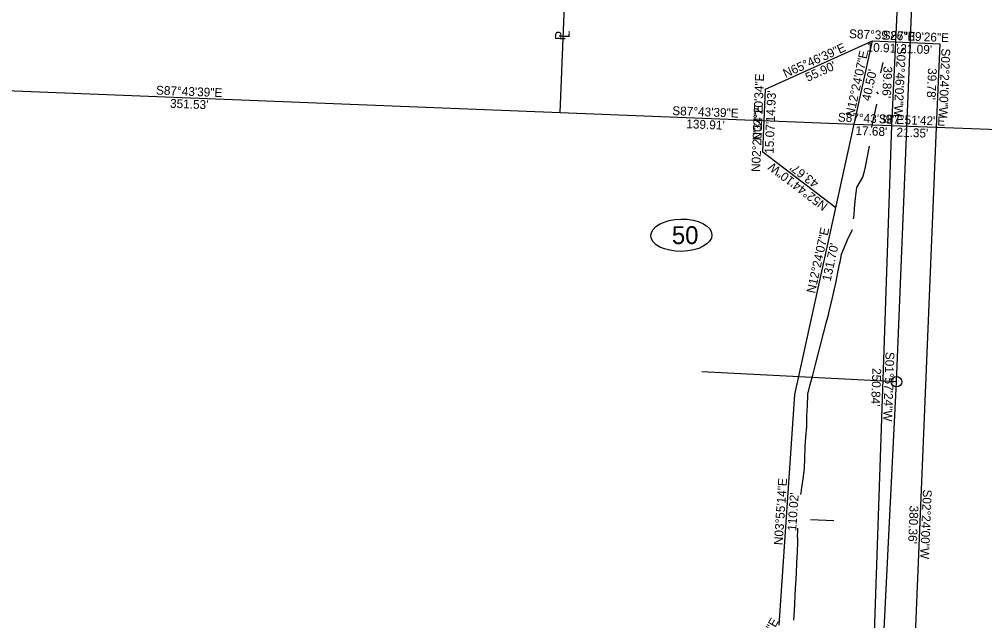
# Model space of a CAD drawing. Extents: x 1145508 to 2262867, y -3126236 to 2021677.
# Drawn here: x 1149967.4 to 1150426.5, y 2019978.9 to 2020265.1 of the extents above; entities that cross this region are included whole.
import ezdxf

# ---------------------------------------------------------------- set-up
doc = ezdxf.new("R2010")
doc.units = 0
for name, color, linetype in [('DSN_RDWY_Alignment', 7, 'Continuous'), ('DSN_RDWY_Const Limits', 7, 'Continuous'), ('DSN_ROW_Annotation', 7, 'Continuous'), ('DSN_ROW_Esmnt', 7, 'Continuous'), ('DSN_ROW_Line', 7, 'Continuous'), ('DSN_ROW_Line-Annotation', 7, 'Continuous'), ('DSN_ROW_Prop-Line', 7, 'Continuous'), ('DSN_ROW_Prop-Line-Annotation', 7, 'Continuous'), ('E_Const Align', 7, 'Continuous'), ('EX_QSECTION', 7, 'Continuous'), ('EX_ROW_ANNOT', 7, 'Continuous'), ('EX_SIGN', 7, 'Continuous')]:
    doc.layers.add(name, color=color, linetype=linetype)

msp = doc.modelspace()

# ---------------------------------------------------------------- linework, layer by layer
at = {"layer": 'DSN_RDWY_Alignment'}
for p, q in [((1150384.54, 2020092.58), (1150392.37, 2020283.97)), ((1150370.24, 2019808.25), (1150384.54, 2020092.58))]:
    msp.add_line(p, q, dxfattribs=at)
msp.add_lwpolyline([(1150384.54, 2020092.58), (1150292.02, 2020097.23)], dxfattribs=at)
msp.add_circle((1150384.54, 2020092.58), 2.5, dxfattribs=at)
at = {"layer": 'DSN_RDWY_Const Limits'}
for points in [[(1150377.02, 2020239.56), (1150378.22, 2020244.51)], [(1150376.04, 2020229.59), (1150375.14, 2020230.54)], [(1150372.84, 2020213.6), (1150372.85, 2020213.71), (1150373.04, 2020214.7), (1150374.15, 2020219.66), (1150375.22, 2020224.62)], [(1150364.16, 2020170.03), (1150364.35, 2020171.9), (1150364.6, 2020175.01), (1150365.1, 2020180), (1150365.68, 2020184.98), (1150368.47, 2020189.87), (1150369.27, 2020192.72), (1150369.79, 2020194.82), (1150370.71, 2020199.78), (1150371.64, 2020204.75)], [(1150338.99, 2020038.86), (1150339.3, 2020040.76), (1150339.38, 2020041.33), (1150339.5, 2020042.14), (1150340.1, 2020046.3), (1150340.81, 2020051.27), (1150341, 2020056.27), (1150341.03, 2020061.28), (1150341.03, 2020062), (1150341.4, 2020066.26), (1150341.84, 2020071.25), (1150341.96, 2020076.25), (1150342.17, 2020081.24), (1150342.31, 2020086.24), (1150342.42, 2020086.68), (1150343.52, 2020091.19), (1150344.43, 2020094.59), (1150344.81, 2020095.76), (1150346.08, 2020100.71), (1150347.29, 2020105.66), (1150347.31, 2020105.75), (1150348.57, 2020110.61), (1150349.86, 2020115.57), (1150351.15, 2020120.52), (1150352.34, 2020125.08), (1150352.43, 2020125.47), (1150353.56, 2020130.43), (1150354.69, 2020135.39), (1150355.82, 2020140.34), (1150356.83, 2020145.31), (1150357.49, 2020148.53), (1150357.84, 2020150.27), (1150358.45, 2020153.25), (1150359.11, 2020155.22), (1150361.22, 2020160.14), (1150363.59, 2020165.05)], [(1150335.68, 2019979.11), (1150335.9, 2019981.43), (1150336.14, 2019986.43), (1150336.39, 2019991.42), (1150336.67, 2019996.41), (1150336.96, 2020001.4), (1150337.18, 2020006.4), (1150337.42, 2020011.39), (1150337.67, 2020016.39), (1150337.69, 2020018.07), (1150337.47, 2020018.86), (1150337.59, 2020021.4), (1150337.67, 2020022.86)]]:
    msp.add_lwpolyline(points, dxfattribs=at)
at = {"layer": 'DSN_ROW_Esmnt'}
for p, q in [((1150322.18, 2020231.79), (1150373.16, 2020254.73)), ((1150321.57, 2020216.88), (1150322.18, 2020231.79)), ((1150320.96, 2020201.82), (1150321.57, 2020216.88)), ((1150355.71, 2020175.38), (1150320.96, 2020201.82))]:
    msp.add_line(p, q, dxfattribs=at)
at = {"layer": 'DSN_ROW_Line'}
for p, q in [((1150364.46, 2020215.17), (1150373.16, 2020254.73)), ((1150373.16, 2020254.73), (1150384.06, 2020254.28)), ((1150384.06, 2020254.28), (1150405.14, 2020253.42)), ((1150405.14, 2020253.42), (1150403.47, 2020213.68)), ((1150336.18, 2020086.55), (1150364.46, 2020215.17)), ((1150403.47, 2020213.68), (1150387.54, 2019833.65)), ((1150328.66, 2019976.79), (1150336.18, 2020086.55))]:
    msp.add_line(p, q, dxfattribs=at)
at = {"layer": 'DSN_ROW_Line-Annotation'}
msp.add_ellipse((1150282.23, 2020162.3), major_axis=(14.54, 0.23), ratio=0.529773, dxfattribs=at)
at = {"layer": 'DSN_ROW_Prop-Line'}
msp.add_line((1150224.66, 2020220.72), (1150230.15, 2020357.67), dxfattribs=at)
at = {"layer": 'E_Const Align'}
msp.add_arc((1156951.39, 2010282.18), 11459.16, 121.829445, 126.548983, dxfattribs=at)
msp.add_arc((1156951.39, 2010282.18), 11459.16, 121.829445, 126.548983, dxfattribs=at)
at = {"layer": 'EX_QSECTION'}
for p, q in [((1150388.75, 2020351.41), (1150384.06, 2020254.28)), ((1150384.06, 2020254.28), (1150382.13, 2020214.47)), ((1149873.41, 2020234.66), (1150224.66, 2020220.72)), ((1150224.66, 2020220.72), (1150364.46, 2020215.17)), ((1150364.46, 2020215.17), (1150382.13, 2020214.47)), ((1150382.13, 2020214.47), (1150373.57, 2019963.78)), ((1150382.13, 2020214.47), (1150403.47, 2020213.68)), ((1150403.47, 2020213.68), (1150507.05, 2020209.81))]:
    msp.add_line(p, q, dxfattribs=at)
at = {"layer": 'EX_SIGN'}
msp.add_line((1150343.67, 2020027.02), (1150354.74, 2020026.58), dxfattribs=at)

# ---------------------------------------------------------------- texts
at = {"layer": 'DSN_ROW_Annotation'}
for s, rotation, p in [('S87°39\'26"E', 357.6573, (1150361.9, 2020256.09)), ('S87°39\'26"E', 357.6573, (1150377.89, 2020255.44)), ('N65°46\'39"E', 24.2224, (1150331.75, 2020237.09)), ("10.91'", 357.6573, (1150370.25, 2020249.74)), ("21.09'", 357.6573, (1150386.24, 2020249.09)), ('S02°24\'00"W', 267.6, (1150405.95, 2020251.26)), ('N12°24\'07"E', 77.5981, (1150364.27, 2020218.49)), ("55.90'", 24.2224, (1150342.33, 2020235.27)), ("40.50'", 77.5981, (1150372.04, 2020225.89)), ("39.78'", 267.6, (1150399.55, 2020241.91)), ('N02°20\'34"E', 87.6573, (1150320.28, 2020207.33)), ("14.93'", 87.6573, (1150326.64, 2020215.98)), ('N02°20\'34"E', 87.6573, (1150319.67, 2020192.34)), ("15.07'", 87.6573, (1150326.03, 2020200.99)), ('N52°44\'10"W', 142.7362, (1150352.17, 2020176.94)), ("43.67'", 142.7362, (1150347.91, 2020187.72)), ('N12°24\'07"E', 77.5981, (1150345.78, 2020134.4)), ("131.70'", 77.5981, (1150353.19, 2020140.14)), ('N03°55\'14"E', 86.0793, (1150330.35, 2020014.71)), ("110.02'", 86.0793, (1150336.83, 2020021.49)), ('S02°24\'00"W', 267.6, (1150397.15, 2020041.38)), ("380.36'", 267.6, (1150390.82, 2020033.73)), ('N29°26\'39"E', 60.5559, (1150313.03, 2019950.93))]:
    msp.add_text(s, height=4.2, rotation=rotation, dxfattribs=at).set_placement(p)
at = {"layer": 'DSN_ROW_Line-Annotation'}
msp.add_text('50', height=8.5, dxfattribs=at).set_placement((1150277.72, 2020158.09))
at = {"layer": 'DSN_ROW_Prop-Line-Annotation'}
for s, p in [('L', (1150229.02, 2020256.02)), ('P', (1150227.06, 2020254.94))]:
    msp.add_text(s, height=5, rotation=87.5589, dxfattribs=at).set_placement(p)
at = {"layer": 'EX_ROW_ANNOT'}
for s, rotation, p in [('S02°46\'02"W', 267.2328, (1150384.85, 2020252.08)), ('S02°46\'02"W', 267.2328, (1150384.85, 2020252.08)), ("39.86'", 267.2328, (1150378.4, 2020242.77)), ("39.86'", 267.2328, (1150378.4, 2020242.77)), ('S87°43\'39"E', 357.7276, (1150032.32, 2020229.25)), ('S87°43\'39"E', 357.7276, (1150032.32, 2020229.25)), ("351.53'", 357.7276, (1150038.98, 2020222.98)), ("351.53'", 357.7276, (1150038.98, 2020222.98)), ('S87°43\'39"E', 357.7276, (1150277.85, 2020219.51)), ('S87°43\'39"E', 357.7276, (1150277.85, 2020219.51)), ('S87°43\'39"E', 357.7276, (1150356.59, 2020216.39)), ('S87°43\'39"E', 357.7276, (1150356.59, 2020216.39)), ('S87°51\'42"E', 357.8615, (1150376.08, 2020215.6)), ('S87°51\'42"E', 357.8615, (1150376.08, 2020215.6)), ("139.91'", 357.7276, (1150284.51, 2020213.24)), ("139.91'", 357.7276, (1150284.51, 2020213.24)), ("17.68'", 357.7276, (1150364.95, 2020210.05)), ("17.68'", 357.7276, (1150364.95, 2020210.05)), ("21.35'", 357.8615, (1150384.46, 2020209.28)), ("21.35'", 357.8615, (1150384.46, 2020209.28)), ('S01°57\'24"W', 268.0433, (1150379.36, 2020106.86)), ('S01°57\'24"W', 268.0433, (1150379.36, 2020106.86)), ("250.84'", 268.0433, (1150373.09, 2020099.15)), ("250.84'", 268.0433, (1150373.09, 2020099.15))]:
    msp.add_text(s, height=4.2, rotation=rotation, dxfattribs=at).set_placement(p)

doc.saveas('drawing.dxf')
